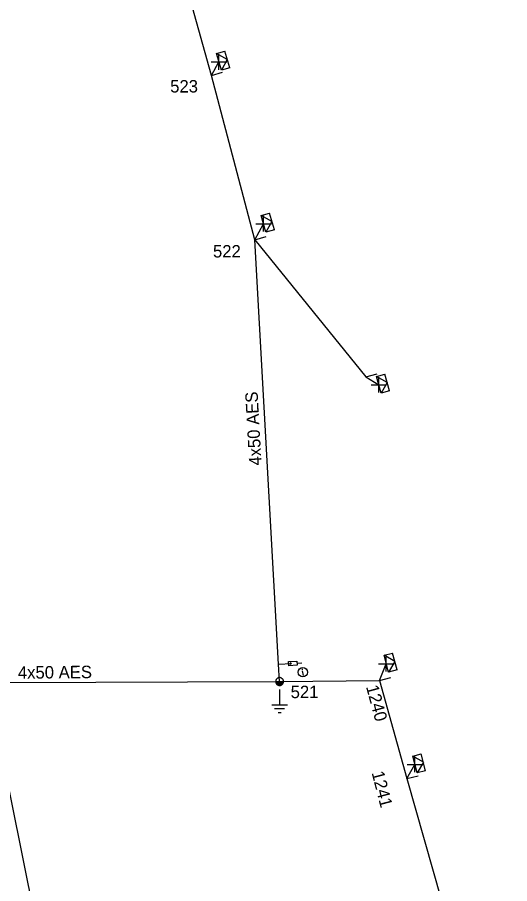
# Model space of a CAD drawing. Extents: x -540466 to -537383, y -1184038 to -1179972.
# Drawn here: x -539043.6 to -539004.1, y -1180471.8 to -1180402.2 of the extents above; entities that cross this region are included whole.
import ezdxf

# ---------------------------------------------------------------- set-up
doc = ezdxf.new("R2010")
doc.units = 0
for name, color, linetype in [('Vrstva 1', 7, 'Continuous'), ('Vrstva 10', 7, 'Continuous'), ('Vrstva 13', 7, 'Continuous'), ('Vrstva 14', 7, 'Continuous'), ('Vrstva 15', 7, 'Continuous'), ('Vrstva 16', 7, 'Continuous'), ('Vrstva 2', 7, 'Continuous'), ('Vrstva 31', 7, 'Continuous'), ('Vrstva 34', 7, 'Continuous'), ('Vrstva 36', 7, 'Continuous'), ('Vrstva 50', 7, 'Continuous'), ('Vrstva 51', 7, 'Continuous'), ('Vrstva 54', 7, 'Continuous'), ('Vrstva 8', 7, 'Continuous'), ('Vrstva 9', 7, 'Continuous')]:
    doc.layers.add(name, color=color, linetype=linetype)

# ---------------------------------------------------------------- blocks, each defined once
blk = doc.blocks.new('NN440')
at = {"layer": 'Vrstva 2'}
for points in [[(0.63, 0), (0.63, 0.06), (0.62, 0.13), (0.6, 0.19), (0.58, 0.25), (0.55, 0.31), (0.51, 0.37), (0.47, 0.42), (0.42, 0.46), (0.37, 0.51), (0.32, 0.54), (0.26, 0.57), (0.2, 0.59), (0.13, 0.61), (0.07, 0.62), (0, 0.63), (-0.06, 0.62), (-0.13, 0.61), (-0.19, 0.59), (-0.26, 0.57), (-0.31, 0.54), (-0.37, 0.51), (-0.42, 0.46), (-0.47, 0.42), (-0.51, 0.37), (-0.54, 0.31), (-0.57, 0.25), (-0.6, 0.19), (-0.62, 0.13), (-0.63, 0.06), (-0.63, 0), (-0.63, -0.07), (-0.62, -0.14), (-0.6, -0.2), (-0.57, -0.26), (-0.54, -0.32), (-0.51, -0.37), (-0.47, -0.43), (-0.42, -0.47), (-0.37, -0.51), (-0.31, -0.55), (-0.26, -0.58), (-0.19, -0.6), (-0.13, -0.62), (-0.06, -0.63), (0, -0.63), (0.07, -0.63), (0.13, -0.62), (0.2, -0.6), (0.26, -0.58), (0.32, -0.55), (0.37, -0.51), (0.42, -0.47), (0.47, -0.43), (0.51, -0.37), (0.55, -0.32), (0.58, -0.26), (0.6, -0.2), (0.62, -0.14), (0.63, -0.07), (0.63, 0)], [(-0.63, 0), (0.63, 0)], [(-0.6, -0.18), (0.57, -0.18)], [(-0.51, -0.32), (0.5, -0.32)], [(-0.37, -0.47), (0.35, -0.47)]]:
    blk.add_lwpolyline(points, dxfattribs=at)
blk = doc.blocks.new('NN770')
at = {"layer": 'Vrstva 10'}
for p, q in [((0.002, 0.187), (0.002, 0.263)), ((0.002, -0.276), (0.002, 0.111))]:
    blk.add_line(p, q, dxfattribs=at)
blk.add_circle((0, -0.008), 0.375, dxfattribs=at)
blk = doc.blocks.new('NN800')
at = {"layer": 'Vrstva 1'}
for points in [[(-0.442, 0.442), (0.442, -0.442)], [(-0.442, -0.442), (0.442, 0.442)]]:
    blk.add_lwpolyline(points, dxfattribs=at)
blk = doc.blocks.new('NN820')
at = {"layer": 'Vrstva 13'}
for points in [[(-0.003, 0.004), (-0.003, -1.049)], [(-0.165, -0.813), (0.165, -0.813)], [(-0.165, -1.473), (-0.165, -0.813)], [(-0.003, -1.049), (-0.062, -0.926)], [(-0.003, -1.049), (0.057, -0.926)], [(0.165, -0.813), (0.165, -1.473)], [(0.165, -1.473), (-0.165, -1.473)], [(-0.003, -1.473), (-0.003, -1.871)]]:
    blk.add_lwpolyline(points, dxfattribs=at)
blk = doc.blocks.new('NN630')
at = {"layer": 'Vrstva 9'}
for points in [[(-0.003, -0.7), (-0.703, 0)], [(-0.703, -0.7), (-0.703, 0), (0.697, 0), (0.697, -0.7)], [(-0.003, -0.7), (0.697, 0)], [(-0.703, -0.7), (0.697, -0.7)]]:
    blk.add_lwpolyline(points, dxfattribs=at)
blk = doc.blocks.new('NN810')
at = {"layer": 'Vrstva 14'}
for points in [[(0.004, -0.64), (0.004, -1.89)], [(0.629, -1.89), (-0.621, -1.89)], [(0.388, -2.2), (-0.399, -2.2)], [(0.004, -2.515), (-0.124, -2.515)], [(0.137, -2.515), (0.004, -2.515)]]:
    blk.add_lwpolyline(points, dxfattribs=at)
blk = doc.blocks.new('NN510')
at = {"layer": 'Vrstva 2'}
blk.add_lwpolyline([(0.001, 0.002), (0.001, 0.939)], dxfattribs=at)

msp = doc.modelspace()

# ---------------------------------------------------------------- linework, layer by layer
at = {"layer": 'Vrstva 50'}
for points in [[(-539022.55, -1180455.539), (-539022.628, -1180454.153), (-539024.535, -1180420.073), (-539028.021, -1180406.893), (-539031.255, -1180395.273), (-539033.65, -1180386.796), (-539040.652, -1180364.388), (-539040.951, -1180357.426)], [(-539047.022, -1180455.462), (-539046.922, -1180455.444), (-539045.745, -1180455.623), (-539044.672, -1180455.619), (-539022.549, -1180455.539)], [(-539046.887, -1180456.134), (-539045.943, -1180455.937), (-539042.247, -1180474.305), (-539035.203, -1180506.397), (-539031.216, -1180516.578), (-539023.909, -1180536.285)], [(-539022.549, -1180455.539), (-539014.537, -1180455.453), (-539012.348, -1180463.337), (-539006.78, -1180482.911), (-539004.091, -1180492.074)]]:
    msp.add_lwpolyline(points, dxfattribs=at)
at = {"layer": 'Vrstva 54'}
for points in [[(-539024.535, -1180420.073), (-539023.834, -1180418.793)], [(-539014.537, -1180455.453), (-539013.99, -1180454.108)], [(-539012.348, -1180463.337), (-539011.686, -1180462.195)]]:
    msp.add_lwpolyline(points, dxfattribs=at)
at = {"layer": 'Vrstva 8'}
for points in [[(-539028.021, -1180406.893), (-539027.415, -1180405.805)], [(-539024.535, -1180420.073), (-539015.633, -1180431.085), (-539014.59, -1180431.725)]]:
    msp.add_lwpolyline(points, dxfattribs=at)

# ---------------------------------------------------------------- block references
at = {"layer": 'Vrstva 13'}
for p, rotation in [((-539028.021, -1180406.892), -73.53715278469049), ((-539024.536, -1180420.073), -74.38667784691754), ((-539015.634, -1180431.085), -74.1880999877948), ((-539014.537, -1180455.453), -74.80338890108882), ((-539012.349, -1180463.336), -75.51329998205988)]:
    msp.add_blockref('NN510', p, dxfattribs=dict(at, rotation=rotation))
at = {"layer": 'Vrstva 13', "xscale": 0.5, "yscale": 0.5, "rotation": -0.9238916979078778}
msp.add_blockref('NN440', (-539022.549, -1180455.539), dxfattribs=at)
at = {"layer": 'Vrstva 15'}
msp.add_blockref('NN810', (-539022.549, -1180455.539), dxfattribs=at)
at = {"layer": 'Vrstva 16', "rotation": 93.2029727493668}
msp.add_blockref('NN820', (-539022.628, -1180454.153), dxfattribs=at)
at = {"layer": 'Vrstva 31'}
for p, rotation in [((-539027.415, -1180405.805), 106.46284721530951), ((-539023.834, -1180418.793), 105.61332215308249), ((-539014.59, -1180431.725), 105.81190007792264), ((-539013.989, -1180454.109), 105.19661109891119), ((-539011.686, -1180462.195), 104.48669995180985)]:
    msp.add_blockref('NN630', p, dxfattribs=dict(at, rotation=rotation))
at = {"layer": 'Vrstva 34'}
for p, rotation in [((-539027.415, -1180405.805), 45), ((-539023.834, -1180418.793), 45), ((-539014.59, -1180431.725), 45), ((-539013.99, -1180454.109), 44.99999995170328), ((-539011.686, -1180462.195), 45)]:
    msp.add_blockref('NN800', p, dxfattribs=dict(at, rotation=rotation))
at = {"layer": 'Vrstva 36', "rotation": 8.746161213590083}
msp.add_blockref('NN770', (-539020.686, -1180454.788), dxfattribs=at)

# ---------------------------------------------------------------- texts
at = {"layer": 'Vrstva 14'}
for s, p in [('523', (-539031.327, -1180408.26)), ('522', (-539027.894, -1180421.503)), ('521', (-539021.663, -1180456.874))]:
    msp.add_text(s, height=1, dxfattribs=at).set_placement(p)
for s, rotation, p in [('1240', 285.197, (-539015.624, -1180455.959)), ('1241', 284.487, (-539015.173, -1180462.86))]:
    msp.add_text(s, height=1, rotation=rotation, dxfattribs=at).set_placement(p)
at = {"layer": 'Vrstva 51'}
for rotation, p in [(93.193, (-539023.987, -1180438.181)), (0.509, (-539043.543, -1180455.319))]:
    msp.add_text('4x50 AES', height=1, rotation=rotation, dxfattribs=at).set_placement(p)

doc.saveas('drawing.dxf')
